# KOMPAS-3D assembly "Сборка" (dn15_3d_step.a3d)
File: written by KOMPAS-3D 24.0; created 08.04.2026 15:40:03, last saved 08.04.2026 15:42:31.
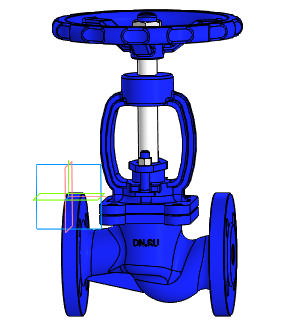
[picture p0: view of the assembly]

Document properties: Автор: R2D2; Полное имя файла: E:\Работа\Зайцев\VSO3131M-F-S Клапан запорный DN.ru Ду15-100 Ру40\DN15\исходные материалы\dn15_3d_step.a3d

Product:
- Component [detail]: Деталь1  | qty 1  | Масса: 3.613832; Автор: R2D2; source file: Деталь1 Деталь1.m3d
- Component [detail]: Деталь2  | qty 1  | Масса: 0.692996; Автор: R2D2; source file: Деталь2 Деталь2.m3d
- Component [detail]: ANSI B18.2.4.2M - M14x2 - 21  | designation ANSI B18.2.4.2M - M14x2  | qty 1  | Масса: 0.029972; Автор: R2D2; source file: ANSI B18.2.4.2M - M14x2 ANSI B18.2.4.2M - M14x2 - 21.m3d
- Component [detail]: ANSI B18.2.4.2M - M6x1 - 10  | designation ANSI B18.2.4.2M - M6x1  | qty 1  | Масса: 0.003008; Автор: R2D2; source file: ANSI B18.2.4.2M - M6x1 ANSI B18.2.4.2M - M6x1 - 10.m3d
- Component [detail]: ANSI B18.2.4.2M - M6x1 - 10  | designation ANSI B18.2.4.2M - M6x1  | qty 1  | Масса: 0.003008; Комментарий: Типы метрических   шестигранных гаек   2; Автор: R2D2; additional columns: Сталь, мягкая; source file: ANSI B18.2.4.2M - M6x1 ANSI B18.2.4.2M - M6x1 - 10.m3d
- Part/product: Сборка
    Масса: 4.342816

Referenced files in E:\Работа\Зайцев\VSO3131M-F-S Клапан запорный DN.ru Ду15-100 Ру40\DN15\исходные материалы\: Деталь1 Деталь1.m3d, Деталь2 Деталь2.m3d, ANSI B18.2.4.2M - M14x2 ANSI B18.2.4.2M - M14x2 - 21.m3d, ANSI B18.2.4.2M - M6x1 ANSI B18.2.4.2M - M6x1 - 10.m3d
Referenced files in E:\Работа\Зайцев\VSO1121M-F-S Клапан запорный сальниковый DN.ru\DN15\исходные материалы\: ANSI B18.2.4.2M - M6x1 ANSI B18.2.4.2M - M6x1 - 10.m3d
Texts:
  Деталь1 Деталь1
  Деталь2 Деталь2
  ANSI B18.2.4.2M - M14x2 ANSI B18.2.4.2M - M14x2 - 21
  ANSI B18.2.4.2M - M6x1 ANSI B18.2.4.2M - M6x1 - 10 (1)
  ANSI B18.2.4.2M - M6x1 ANSI B18.2.4.2M - M6x1 - 10 (2)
